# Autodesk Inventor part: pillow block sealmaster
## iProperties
Shininess: 20.0
PropertySet Name: _Private Model Information
Created: 2001-01
Part Number: pillow block sealmaster
Document SubType Name: Modeling
Designer: rmjbm2
Control State: 0
Master: False
Checked Out: False
PropertySet Name: Design Tracking Control
Density: 0.0
Volumn: 0.0
Area: 0.0
PropertySet Name: Model Information
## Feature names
1. Extrusion1
2. Extrusion2
3. Fillet1
4. Extrusion3
5. Extrusion4
6. Extrusion5
7. Extrusion6
8. Extrusion7
9. Extrusion8
10. Extrusion9
11. Mirror1
12. Fillet2
13. Fillet3
14. Fillet4
15. Fillet5
16. Hole1
17. Circular Pattern1
18. Mirror2
19. Revolution1
